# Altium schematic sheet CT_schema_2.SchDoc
size 271 x 229 mm
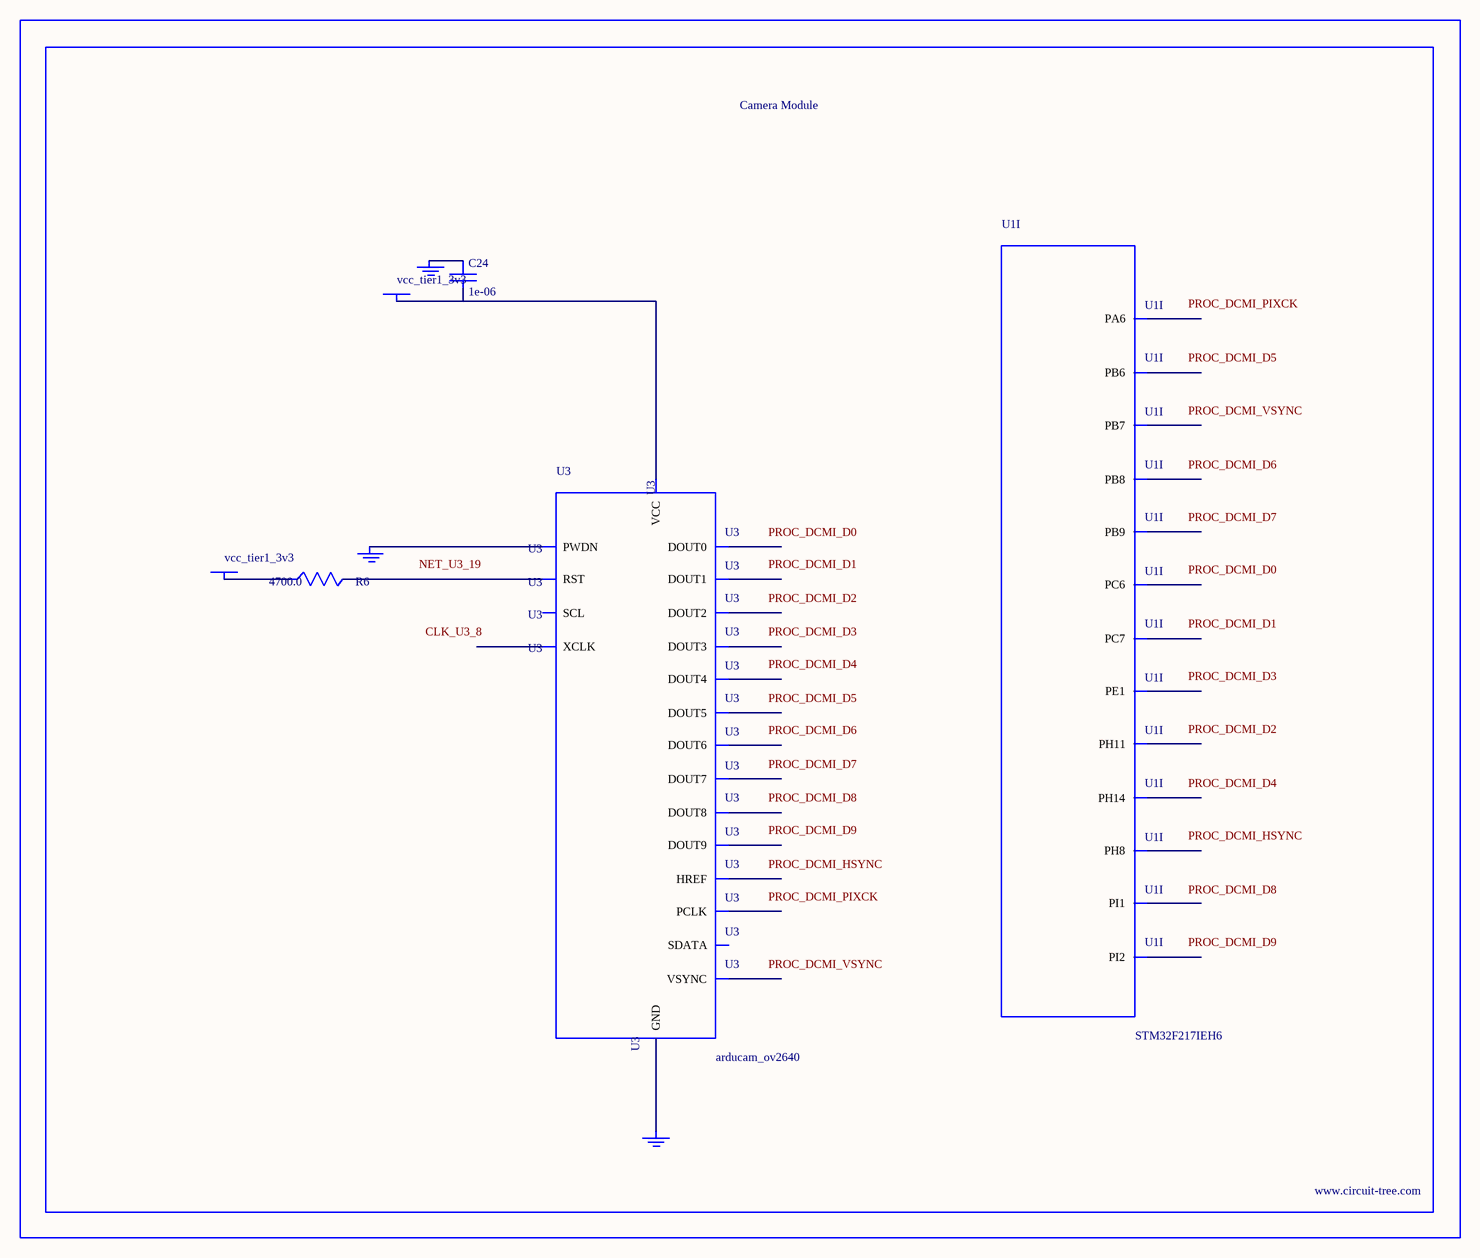
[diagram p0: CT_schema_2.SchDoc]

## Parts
BORDER1  (no value)
C24  1e-06  [C0603]
GND_INSTANCE_1_0  (no value)
GND_INSTANCE_1_1  (no value)
GND_INSTANCE_1_2  (no value)
POWER_INSTANCE_1_0  vcc_tier1_3v3
POWER_INSTANCE_1_1  vcc_tier1_3v3
R6  4700.0  [R0603]
U1  STM32F217IEH6  [UFBGA176_25]  (part I of 14)
U3  arducam_ov2640  [ARDUCAM]

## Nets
NetC24_1: C24.1 GND_INSTANCE_1_0.0(GND)
NetC24_2: C24.2 POWER_INSTANCE_1_0.0(PWR) U3.1(VCC)
NetGND_INSTANCE_1_1_0: GND_INSTANCE_1_1.0(GND) U3.20(PWDN)
NetGND_INSTANCE_1_2_0: GND_INSTANCE_1_2.0(GND) U3.2(GND)
NetPOWER_INSTANCE_1_1_0: POWER_INSTANCE_1_1.0(PWR) R6.1
NetR6_2: R6.2 U3.19(RST)

Not connected (* = marked no-connect by the designer): U1 A3(PE1) A5(PB8) B4(PB9) B5(PB7) B6(PB6) C14(PI2) D14(PI1) E13(PH14) G15(PC7) H15(PC6) L12(PH11) M12(PH8) P3(PA6); U3 3(SCL) 4(SDATA) 5(VSYNC) 6(HREF) 7(PCLK) 8(XCLK) 9(DOUT9) 10(DOUT8) 11(DOUT7) 12(DOUT6) 13(DOUT5) 14(DOUT4) 15(DOUT3) 16(DOUT2) 17(DOUT1) 18(DOUT0)

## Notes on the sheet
- Labels drawn without touching a wire or pin: CLK_U3_8, NET_U3_19, PROC_DCMI_D0, PROC_DCMI_D1, PROC_DCMI_D2, PROC_DCMI_D3, PROC_DCMI_D4, PROC_DCMI_D5, PROC_DCMI_D6, PROC_DCMI_D7, PROC_DCMI_D8, PROC_DCMI_D9, PROC_DCMI_HSYNC, PROC_DCMI_PIXCK, PROC_DCMI_VSYNC

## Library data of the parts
BORDER1 = BORDER_PAGE1
C24 = C0603C105K3RACTU
GND_INSTANCE_1_0-GND_INSTANCE_1_2 = GND
POWER_INSTANCE_1_0 POWER_INSTANCE_1_1 = PWR
R6 = RC0603JR-074K7L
